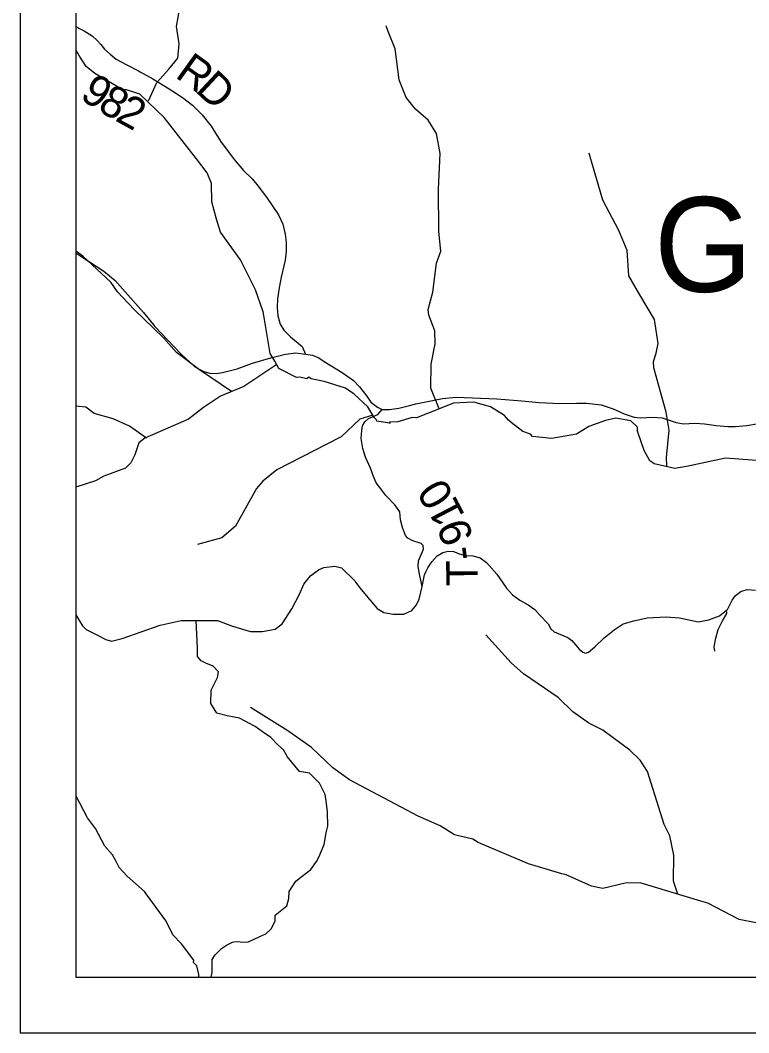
# Model space of a CAD drawing. Extents: x -1.8 to 75.7, y -2 to 25.
# Drawn here: x 43.7 to 45.012, y 15.612 to 17.434 of the extents above; entities that cross this region are included whole.
import ezdxf

# ---------------------------------------------------------------- set-up
doc = ezdxf.new("R2010")
doc.units = 0
for name, color, linetype in [('GM_X_County_Road', 7, 'Continuous'), ('GM_X_Minor_River', 7, 'Continuous'), ('GM_X_Township', 7, 'Continuous'), ('GM_X_Township_Road', 7, 'Continuous'), ('GM_X_Township_Road_Text', 7, 'Continuous'), ('GM_X_Township_ROW', 7, 'Continuous'), ('GM_X_Township_Text', 7, 'Continuous'), ('SH_Data', 7, 'Continuous')]:
    doc.layers.add(name, color=color, linetype=linetype)

msp = doc.modelspace()

# ---------------------------------------------------------------- linework, layer by layer
at = {"layer": 'GM_X_County_Road'}
for points in [[(43.8002, 17.0156), (43.8092, 17.01), (43.8508, 16.9825), (43.871, 16.9657), (43.8889, 16.9456), (43.9222, 16.9087), (43.9423, 16.8833), (43.9895, 16.8339), (44.0127, 16.8124), (44.0223, 16.8062), (44.0305, 16.8021), (44.0417, 16.799), (44.053, 16.7985), (44.0645, 16.8002), (44.0906, 16.8072), (44.1181, 16.8172), (44.1514, 16.827), (44.178, 16.8335), (44.1964, 16.8361), (44.2139, 16.8335)], [(44.2139, 16.8335), (44.2266, 16.8316), (44.2379, 16.8266), (44.2477, 16.8203), (44.2798, 16.8002), (44.3001, 16.7858), (44.3112, 16.7748), (44.3241, 16.7578), (44.3315, 16.7473), (44.3437, 16.7382), (44.3518, 16.7337), (44.365, 16.7339), (44.3816, 16.7365), (44.4011, 16.7413)], [(44.4011, 16.7413), (44.4125, 16.7442), (44.4604, 16.7537), (44.4851, 16.7558), (44.5586, 16.753), (44.6034, 16.7493), (44.6348, 16.7465), (44.6718, 16.7449), (44.7022, 16.745), (44.7193, 16.7451), (44.72, 16.745)], [(44.72, 16.745), (44.7463, 16.7425), (44.7679, 16.7349), (44.7874, 16.7258), (44.8058, 16.72), (44.8172, 16.719), (44.8398, 16.7202), (44.8558, 16.7188), (44.867, 16.7153), (44.8812, 16.7107), (44.8947, 16.7083), (44.9149, 16.709), (44.9323, 16.7079), (44.9535, 16.7051), (44.974, 16.7032), (44.9872, 16.703), (45.0082, 16.7053), (45.0296, 16.7086)]]:
    msp.add_lwpolyline(points, dxfattribs=at)
at = {"layer": 'GM_X_Minor_River'}
for points in [[(43.9314, 17.2896), (43.9461, 17.3223), (43.968, 17.3463), (43.9837, 17.3659), (43.9864, 17.392), (43.9817, 17.423), (43.9876, 17.4566), (44.0044, 17.4875), (44.0064, 17.5034), (43.9791, 17.5738), (43.9656, 17.6167), (43.949, 17.7031), (43.9344, 17.7465), (43.9226, 17.7685), (43.8712, 17.8202), (43.8666, 17.8306), (43.8653, 17.8356), (43.8576, 17.856), (43.8528, 17.8865), (43.8817, 17.9274), (43.8863, 17.9318)], [(44.4545, 16.7352), (44.4393, 16.772), (44.4399, 16.8153), (44.4474, 16.8519), (44.4466, 16.8754), (44.4358, 16.9039), (44.4349, 16.9138), (44.4431, 16.945), (44.4496, 16.9972), (44.4574, 17.019), (44.4536, 17.0544), (44.4532, 17.1304), (44.4563, 17.1948), (44.4498, 17.2307), (44.4347, 17.2544), (44.4118, 17.2745), (44.3951, 17.2951), (44.3842, 17.3224), (44.3824, 17.327), (44.3755, 17.3831), (44.3624, 17.4139), (44.3593, 17.4246)], [(44.3652, 16.7109), (44.3659, 16.7087), (44.3656, 16.7109), (44.3648, 16.709), (44.3421, 16.7128), (44.3417, 16.7154), (44.3376, 16.7196), (44.3262, 16.7386), (44.3013, 16.7617), (44.2861, 16.7723), (44.2472, 16.7844), (44.2241, 16.7889), (44.2196, 16.7923), (44.2162, 16.7889), (44.2037, 16.7923), (44.1973, 16.7915), (44.1659, 16.8077), (44.1583, 16.8207), (44.15, 16.8347), (44.1386, 16.9031), (44.1378, 16.9095), (44.1238, 16.949), (44.0969, 17.0033), (44.0609, 17.053), (44.0537, 17.0762), (44.0454, 17.1077), (44.0446, 17.1408), (44.0366, 17.1598), (44.0173, 17.1852), (43.9591, 17.2591), (43.9156, 17.3012), (43.8917, 17.3092), (43.8838, 17.3095), (43.8346, 17.3387), (43.8191, 17.3512), (43.807, 17.3698), (43.8036, 17.3751), (43.8002, 17.3809)], [(44.8642, 16.6317), (44.8638, 16.6473), (44.8687, 16.6969), (44.8633, 16.7293), (44.8411, 16.8086), (44.8403, 16.82), (44.8449, 16.8351), (44.8488, 16.8524), (44.8422, 16.8959), (44.8156, 16.9401), (44.7958, 16.9741), (44.7931, 17.0197), (44.7779, 17.0559), (44.7489, 17.1104), (44.7291, 17.1782), (44.7278, 17.1843), (44.7243, 17.1954)], [(44.0807, 16.7661), (44.0227, 16.8054), (43.9813, 16.8367), (43.9579, 16.8629), (43.905, 16.9136), (43.875, 16.9457), (43.863, 16.9627), (43.813, 17.0099), (43.8002, 17.0185)], [(44.1619, 16.8146), (44.103, 16.7751), (44.0605, 16.7579), (44.0304, 16.7376), (44.003, 16.7164), (43.9248, 16.6824), (43.9136, 16.6737), (43.9065, 16.6523), (43.8993, 16.6377), (43.8899, 16.6285), (43.8505, 16.6138), (43.8355, 16.6052), (43.8002, 16.5938)], [(43.9275, 16.6824), (43.8971, 16.7038), (43.8677, 16.7169), (43.8332, 16.7268), (43.818, 16.7379), (43.8002, 16.74)], [(45.0256, 16.6423), (44.9701, 16.646), (44.9028, 16.6321), (44.879, 16.6275), (44.8416, 16.6361), (44.8393, 16.6377), (44.834, 16.6414), (44.8238, 16.66), (44.8113, 16.6946), (44.8116, 16.7018), (44.7995, 16.7132), (44.7727, 16.7181), (44.7538, 16.7138), (44.7239, 16.7031), (44.7016, 16.6897), (44.6574, 16.6816), (44.6223, 16.685), (44.6192, 16.6895), (44.6052, 16.6944), (44.5841, 16.7103), (44.5795, 16.7149), (44.5719, 16.7229), (44.5466, 16.7388), (44.5171, 16.747), (44.4801, 16.7454), (44.4332, 16.7267), (44.4139, 16.719), (44.406, 16.7194), (44.3799, 16.7114), (44.3652, 16.7109)], [(44.3352, 16.7237), (44.3118, 16.7164), (44.2779, 16.6845), (44.2522, 16.6716), (44.162, 16.6251), (44.1372, 16.6047), (44.1254, 16.5914), (44.0875, 16.5239), (44.063, 16.5026), (44.0192, 16.4907)], [(44.884, 15.8616), (44.8766, 15.8852), (44.8769, 15.9319), (44.8696, 15.9663), (44.8593, 15.9871), (44.8293, 16.0823), (44.8163, 16.1028), (44.7979, 16.1208), (44.7491, 16.1569), (44.7242, 16.1691), (44.6949, 16.1894), (44.6689, 16.2153), (44.6063, 16.2583), (44.5842, 16.278), (44.5385, 16.3284)], [(45.0251, 15.8099), (44.9947, 15.8158), (44.9381, 15.8453), (44.9258, 15.8491), (44.8164, 15.8818), (44.7892, 15.8815), (44.7492, 15.8718), (44.7289, 15.8758), (44.6834, 15.8963), (44.6755, 15.8984), (44.6152, 15.9163), (44.5245, 15.9545), (44.5149, 15.9605), (44.4818, 15.968), (44.4563, 15.9847), (44.4167, 16.0019), (44.2932, 16.0674), (44.2629, 16.0888), (44.2243, 16.1254), (44.1821, 16.1552), (44.1146, 16.1972)], [(44.013, 15.7425), (43.9907, 15.7721), (43.9748, 15.7884), (43.963, 15.8127), (43.9267, 15.8624), (43.9237, 15.8662), (43.8927, 15.8942), (43.8783, 15.9098), (43.8726, 15.9204), (43.8662, 15.9322), (43.8522, 15.9477), (43.8355, 15.9796), (43.8211, 15.9989), (43.8007, 16.038), (43.8002, 16.0384)], [(44.0219, 15.7121), (44.0217, 15.717), (44.0179, 15.7326), (44.0119, 15.7387), (44.013, 15.7425)]]:
    msp.add_lwpolyline(points, dxfattribs=at)
at = {"layer": 'GM_X_Township'}
msp.add_lwpolyline([(43.8002, 18.978), (43.8002, 15.7121), (47.7632, 15.7121)], dxfattribs=at)
at = {"layer": 'GM_X_Township_Road'}
for points in [[(43.8002, 17.4239), (43.8057, 17.4203), (43.8155, 17.4154), (43.8295, 17.4065), (43.8384, 17.3982), (43.8455, 17.3908), (43.8521, 17.3824), (43.862, 17.3731), (43.8728, 17.3645), (43.892, 17.3542), (43.9131, 17.3431), (43.9162, 17.3414)], [(43.9162, 17.3414), (43.9389, 17.3291), (43.9684, 17.3109), (43.9923, 17.2956), (44.0102, 17.2816), (44.0279, 17.2642), (44.0442, 17.2435), (44.0606, 17.217), (44.0852, 17.1838), (44.1022, 17.1638), (44.1177, 17.1488), (44.1261, 17.139), (44.1435, 17.1161), (44.1649, 17.0844), (44.1728, 17.0672), (44.1774, 17.0495), (44.1792, 17.0347), (44.1792, 17.0185), (44.1772, 17.0025), (44.1701, 16.972), (44.1664, 16.9526), (44.1634, 16.9329), (44.163, 16.9172), (44.1642, 16.9022), (44.1683, 16.8875), (44.1745, 16.8769), (44.1865, 16.8648), (44.2077, 16.8474), (44.2139, 16.8335)], [(44.4236, 16.4151), (44.4192, 16.4374), (44.4165, 16.4513), (44.417, 16.4616), (44.4211, 16.4697), (44.4264, 16.4826), (44.4259, 16.4891), (44.4218, 16.4927), (44.4182, 16.4941), (44.407, 16.4972), (44.3983, 16.502), (44.394, 16.5071), (44.3883, 16.5212), (44.3847, 16.5351), (44.3837, 16.5497), (44.3749, 16.5621), (44.3583, 16.5789), (44.3492, 16.5909), (44.3411, 16.6021), (44.3363, 16.6134), (44.3308, 16.6285), (44.3219, 16.6479), (44.3169, 16.6637), (44.3143, 16.6819), (44.315, 16.6963), (44.3167, 16.7044), (44.3205, 16.7116), (44.327, 16.7178), (44.3442, 16.725), (44.3518, 16.7337)], [(44.3041, 16.4233), (44.3142, 16.4101), (44.3297, 16.3914), (44.3428, 16.3757), (44.3548, 16.3684), (44.3719, 16.3654), (44.3908, 16.3654), (44.4054, 16.372), (44.4138, 16.382), (44.4185, 16.3926), (44.4236, 16.4151), (44.4279, 16.4361), (44.4305, 16.4418), (44.4338, 16.4491), (44.4411, 16.4599), (44.451, 16.4704), (44.4608, 16.4766), (44.4704, 16.4788), (44.4802, 16.4781), (44.4908, 16.474), (44.5008, 16.4711), (44.515, 16.4707), (44.5284, 16.4668), (44.5396, 16.4584), (44.5583, 16.4374), (44.576, 16.4122), (44.5868, 16.4), (44.5995, 16.3904), (44.6146, 16.3823), (44.6266, 16.3737), (44.6359, 16.3636), (44.6505, 16.3483), (44.6554, 16.3393), (44.6618, 16.3337), (44.6862, 16.3236), (44.6932, 16.3178), (44.7006, 16.3097), (44.7068, 16.3025), (44.713, 16.2973), (44.7181, 16.2954), (44.7236, 16.2968), (44.735, 16.3067), (44.7514, 16.3231), (44.7693, 16.3372), (44.7856, 16.3483), (44.8052, 16.3535), (44.829, 16.359), (44.8632, 16.3605), (44.8874, 16.359), (44.9209, 16.3519), (44.9398, 16.355), (44.9595, 16.3622), (44.972, 16.3725), (44.9734, 16.3737), (44.9818, 16.3904), (44.9878, 16.3992), (44.9976, 16.4065), (45.0091, 16.4101), (45.0239, 16.4089)], [(44.0439, 15.7121), (44.0455, 15.7205), (44.0455, 15.7319), (44.0457, 15.7438), (44.051, 15.7526), (44.0625, 15.7636), (44.0714, 15.7695), (44.0823, 15.7753), (44.0848, 15.7756)]]:
    msp.add_lwpolyline(points, dxfattribs=at)
at = {"layer": 'GM_X_Township_ROW'}
for points in [[(43.8002, 16.3652), (43.8003, 16.3645), (43.8057, 16.3551), (43.812, 16.3445), (43.8191, 16.3378), (43.8392, 16.3274), (43.8544, 16.32), (43.8643, 16.3171), (43.8839, 16.3214), (43.9519, 16.3457), (43.9901, 16.3539), (44.0168, 16.3539), (44.0554, 16.3542), (44.0823, 16.3436), (44.1147, 16.334), (44.1357, 16.3345), (44.1589, 16.3385), (44.1719, 16.3483), (44.1892, 16.375), (44.2027, 16.4017), (44.2107, 16.4195), (44.2229, 16.4343), (44.2374, 16.4455), (44.2468, 16.4497), (44.2665, 16.4518), (44.2784, 16.449), (44.3025, 16.4254), (44.3041, 16.4233)], [(44.9509, 16.2989), (44.9497, 16.3068), (44.9528, 16.3224), (44.9569, 16.3377), (44.9645, 16.3535), (44.9722, 16.3669), (44.972, 16.3725)], [(44.0848, 15.7756), (44.0914, 15.7762), (44.101, 15.7751), (44.1103, 15.7755), (44.1201, 15.78), (44.1313, 15.7851), (44.1425, 15.7902), (44.1518, 15.7989), (44.159, 15.8128), (44.159, 15.8238), (44.1802, 15.8407), (44.184, 15.8536), (44.1845, 15.8666), (44.1963, 15.8852), (44.208, 15.8939), (44.2233, 15.9057), (44.2335, 15.9205), (44.2381, 15.9278), (44.2476, 15.9509), (44.2511, 15.9718), (44.2538, 15.984), (44.2535, 16.0099), (44.2508, 16.0292), (44.249, 16.0406), (44.2392, 16.0615), (44.221, 16.079), (44.2028, 16.0825), (44.1808, 16.1091), (44.1794, 16.1117), (44.1744, 16.1212), (44.1641, 16.1304), (44.1516, 16.1433), (44.1361, 16.1539), (44.1232, 16.1634), (44.0948, 16.1783), (44.0728, 16.1824), (44.0542, 16.187), (44.0436, 16.2045), (44.044, 16.2284), (44.0554, 16.2512), (44.057, 16.2619), (44.0475, 16.2718), (44.0346, 16.2775), (44.0259, 16.2813), (44.0195, 16.2892), (44.0191, 16.2965), (44.0191, 16.3045), (44.0168, 16.3539)]]:
    msp.add_lwpolyline(points, dxfattribs=at)
at = {"layer": 'SH_Data'}
for p, q in [((43.7002, 22.6121), (43.7002, 15.6121)), ((43.8002, 22.5121), (43.8002, 15.7121)), ((43.8002, 22.5121), (43.8002, 15.7121)), ((43.8002, 15.7121), (50.6002, 15.7121)), ((43.8002, 15.7121), (43.8002, 15.7121)), ((43.8002, 15.7121), (50.6002, 15.7121)), ((43.8002, 15.7121), (43.8002, 15.7121)), ((43.7002, 15.6121), (50.7002, 15.6121))]:
    msp.add_line(p, q, dxfattribs=at)

# ---------------------------------------------------------------- texts
at = {"layer": 'GM_X_Township_Road_Text'}
for s, rotation, p in [('R', 324.3838, (43.9772, 17.333)), ('9', 326.5091, (43.8053, 17.2944)), ('D', 317.1011, (44.0137, 17.3071)), ('8', 329.4437, (43.8372, 17.2734)), ('2', 331.2715, (43.869, 17.2547)), ('0', 122.7891, (44.4828, 16.5789)), ('1', 117.4816, (44.5018, 16.5429)), ('9', 110.2775, (44.5171, 16.5029)), ('-', 97.1054, (44.5234, 16.466)), ('T', 90.2571, (44.524, 16.4161))]:
    msp.add_text(s, height=0.0568, rotation=rotation, dxfattribs=at).set_placement(p)
at = {"layer": 'GM_X_Township_Text'}
msp.add_text('GUYAN', height=0.17045, rotation=0, dxfattribs=at).set_placement((44.8415, 16.9456))

doc.saveas('drawing.dxf')
